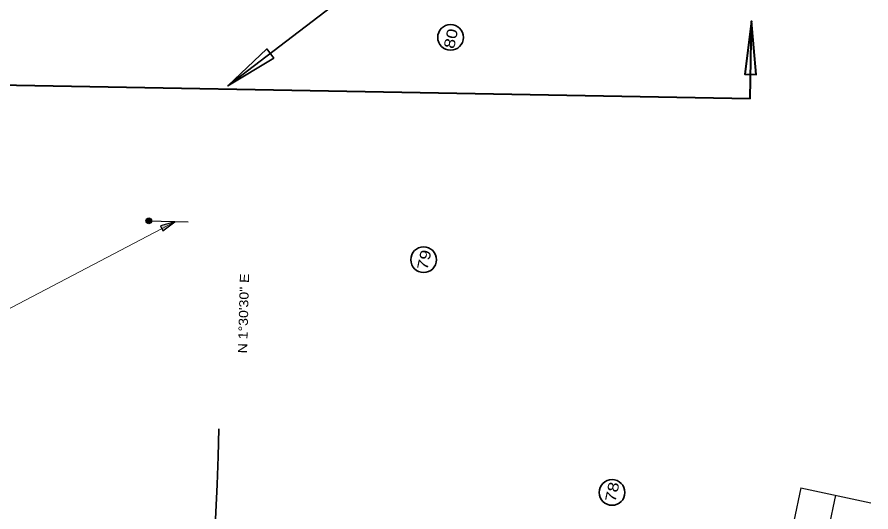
# Model space of a CAD drawing. Extents: x 2363411 to 2369702, y 6977197 to 6988655.
# Drawn here: x 2366110 to 2367231, y 6984748 to 6985397 of the extents above; entities that cross this region are included whole.
import ezdxf
from ezdxf.enums import TextEntityAlignment as Align

# ---------------------------------------------------------------- set-up
doc = ezdxf.new("R2010")
doc.units = 0
doc.header["$LTSCALE"] = 5.6
for name, color, linetype, lineweight in [('1', 7, 'Continuous', 25), ('17', 7, 'Continuous', 35), ('53', 7, 'Continuous', 40), ('55', 7, 'Continuous', 35)]:
    doc.layers.add(name, color=color, linetype=linetype, lineweight=lineweight)
doc.layers.add('28', color=7, linetype='Continuous')

msp = doc.modelspace()

# ---------------------------------------------------------------- hatches: boundary and pattern name
at = {"layer": '1'}
for points in [[(2366284.857, 6985132.927, 1), (2366281.588, 6985126.218, 1)], [(2366317.492, 6985128.147), (2366298.594, 6985123.214), (2366301.665, 6985116.693)]]:
    msp.add_hatch(color=256, dxfattribs=at).paths.add_polyline_path(points)

# ---------------------------------------------------------------- linework, layer by layer
at = {"layer": '1', "lineweight": 13}
msp.add_line((2366317.492, 6985128.147), (2365468.744, 6984684.533), dxfattribs=at)
at = {"layer": '1'}
for p, q in [((2366282.086, 6985129.744), (2366335.063, 6985128.176)), ((2367138.659, 6984779.414), (2367129.448, 6984736.012)), ((2367138.659, 6984779.414), (2367230.644, 6984759.892)), ((2367184.046, 6984769.781), (2367174.834, 6984726.38))]:
    msp.add_line(p, q, dxfattribs=at)
msp.add_lwpolyline([(2366317.492, 6985128.147), (2366298.594, 6985123.214), (2366301.665, 6985116.693)], close=True, dxfattribs=at)
msp.add_circle((2366283.222, 6985129.572), 3.732, dxfattribs=at)
at = {"layer": '1', "lineweight": 35}
msp.add_arc((2359877.328, 6985028.058), 6500, 337.9611, 358.49155, dxfattribs=at)
at = {"layer": '17'}
for centre in [(2366679.076, 6985370.077), (2366643.782, 6985078.631), (2366891.015, 6984773.498)]:
    msp.add_circle(centre, 16.828, dxfattribs=at)
at = {"layer": '53'}
for points in [[(2367072.309, 6985289.554), (2365676.205, 6985314.749), (2365678.044, 6985416.643)], [(2367072.309, 6985289.554), (2367074.148, 6985391.447), (2367064.998, 6985321.641), (2367079.995, 6985321.286), (2367074.148, 6985391.447)]]:
    msp.add_lwpolyline(points, dxfattribs=at)
msp.add_lwpolyline([(2367079.995, 6985321.286), (2367074.148, 6985391.447), (2367064.998, 6985321.641)], close=True, dxfattribs=at)
at = {"layer": '55'}
msp.add_line((2366386.913, 6985306.514), (2367097.355, 6985848.386), dxfattribs=at)
for points in [[(2366386.913, 6985306.514), (2366447.122, 6985343.004), (2366438.025, 6985354.931)], [(2366447.122, 6985343.004), (2366438.025, 6985354.931), (2366386.913, 6985306.514)]]:
    msp.add_lwpolyline(points, close=True, dxfattribs=at)

# ---------------------------------------------------------------- texts
at = {"layer": '17', "width": 1.25}
for s, p in [('80', (2366686.354, 6985367)), ('79', (2366651.378, 6985077.04)), ('78', (2366898.026, 6984772.809))]:
    msp.add_text(s, height=14, rotation=77.939, dxfattribs=at).set_placement(p, align=Align.CENTER)
at = {"layer": '28', "width": 1.15}
msp.add_text('N 1°30\'30" E', height=12, rotation=88.512, dxfattribs=at).set_placement((2366413.483, 6985008.038), align=Align.CENTER)

doc.saveas('drawing.dxf')
